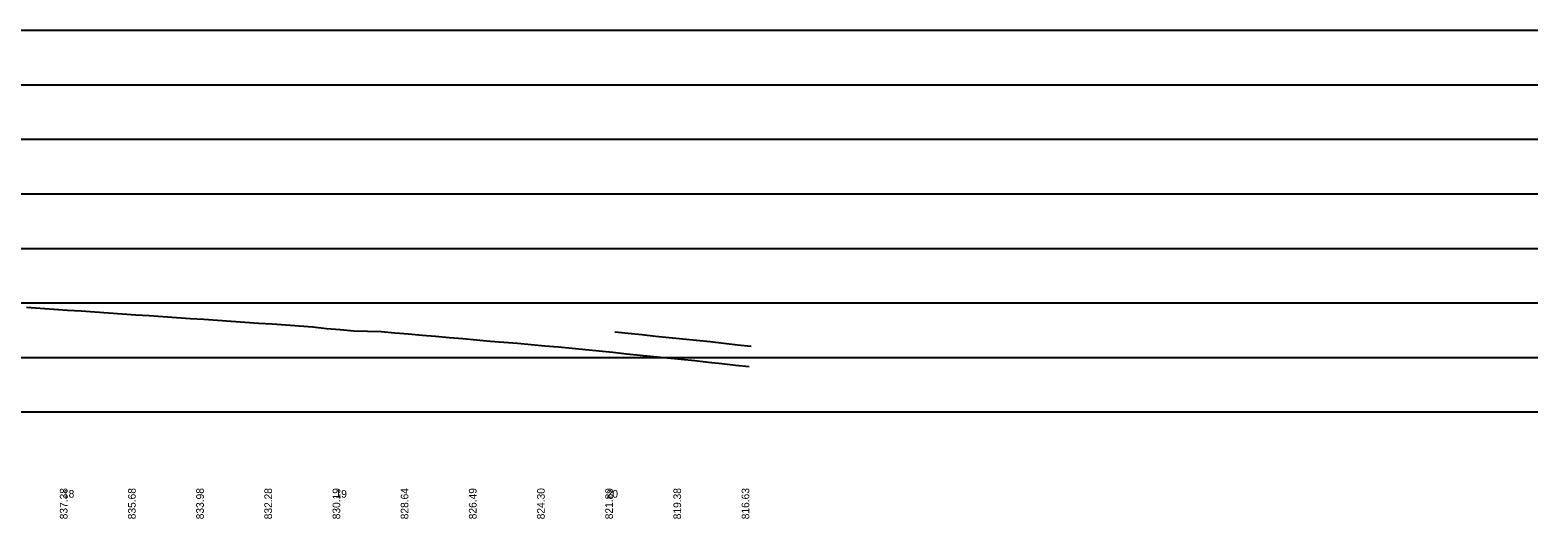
# Model space of a CAD drawing. Extents: x -434 to 1339, y -871 to 603.
# Drawn here: x 786 to 1339, y -539 to -360 of the extents above; entities that cross this region are included whole.
import ezdxf

# ---------------------------------------------------------------- set-up
doc = ezdxf.new("R2010")
doc.units = 0
for name, color, linetype in [('Default', 7, 'Continuous'), ('GK_Cells', 7, 'Continuous'), ('PF_P_Grade_Line', 7, 'Continuous'), ('PF_P_Sta_Elev_Text', 7, 'Continuous'), ('PF_X_Ground_Line', 7, 'Continuous'), ('SC_Scratch1', 7, 'Continuous'), ('SC_Scratch2', 7, 'Continuous')]:
    doc.layers.add(name, color=color, linetype=linetype)

msp = doc.modelspace()

# ---------------------------------------------------------------- linework, layer by layer
at = {"layer": 'GK_Cells'}
msp.add_line((0, -500), (1100, -500), dxfattribs=at)
at = {"layer": 'PF_P_Grade_Line'}
msp.add_lwpolyline([(1000.65, -470.63), (1005.65, -471.14), (1010.65, -471.64), (1015.65, -472.14), (1020.65, -472.64), (1025.65, -473.13), (1030.65, -473.63), (1035.65, -474.19), (1040.65, -474.76), (1045.65, -475.32), (1050.65, -475.88)], dxfattribs=at)
at = {"layer": 'PF_X_Ground_Line'}
msp.add_lwpolyline([(1000, -478.11), (1005, -478.63), (1010, -479.13), (1015, -479.63), (1020, -480.12), (1025, -480.62), (1030, -481.12), (1035, -481.68), (1040, -482.24), (1045, -482.8), (1050, -483.37)], dxfattribs=at)
at = {"layer": 'SC_Scratch1'}
for p, q in [((0, -360), (1339.17, -360)), ((0, -380), (1339.17, -380)), ((0, -400), (1339.17, -400)), ((0, -420), (1339.17, -420)), ((0, -440), (1339.17, -440)), ((0, -460), (1339.17, -460)), ((0, -480), (1339.17, -480)), ((0, -500), (1339.17, -500))]:
    msp.add_line(p, q, dxfattribs=at)
at = {"layer": 'SC_Scratch2'}
msp.add_lwpolyline([(785, -461.61), (790, -461.94), (795, -462.28), (800, -462.62), (805, -462.96), (810, -463.3), (815, -463.64), (820, -463.98), (825, -464.32), (830, -464.66), (835, -465), (840, -465.34), (845, -465.68), (850, -466.02), (855, -466.36), (860, -466.7), (865, -467.04), (870, -467.38), (875, -467.72), (880, -468.06), (885, -468.4), (890, -468.74), (895, -469.39), (900, -469.81), (905, -470.18), (910, -470.34), (915, -470.52), (920, -470.94), (925, -471.36), (930, -471.78), (935, -472.21), (940, -472.64), (945, -473.07), (950, -473.51), (955, -473.97), (960, -474.39), (965, -474.82), (970, -475.24), (975, -475.7), (980, -476.16), (985, -476.62), (990, -477.09), (995, -477.6), (1000, -478.11)], dxfattribs=at)

# ---------------------------------------------------------------- texts
at = {"layer": 'Default'}
for s, p in [('837.38', (800, -539.34)), ('835.68', (825, -539.34)), ('833.98', (850, -539.34)), ('832.28', (875, -539.34)), ('830.19', (900, -539.34)), ('828.64', (925, -539.34)), ('826.49', (950, -539.34)), ('824.30', (975, -539.34)), ('821.89', (1000, -539.34)), ('819.38', (1025, -539.34)), ('816.63', (1050, -539.34))]:
    msp.add_text(s, height=2.8, rotation=90, dxfattribs=at).set_placement(p)
at = {"layer": 'PF_P_Sta_Elev_Text'}
for s, p in [('18', (798.33, -531.4)), ('19', (898.28, -531.4)), ('20', (997.7, -531.4))]:
    msp.add_text(s, height=2.8, dxfattribs=at).set_placement(p)

doc.saveas('drawing.dxf')
